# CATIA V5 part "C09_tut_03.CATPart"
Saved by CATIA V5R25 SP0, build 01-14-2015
Part number: Part1
Bounding box of the stored display mesh (mm): x 0 to 224, y -87.769 to 88.937, z 0 to 67.086
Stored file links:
  E:\ashutosh\Academics\Catia\CATIA V5-6R2013_partfiles\Tutorials_ver_2\C09_tut_03.CATPart
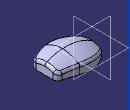
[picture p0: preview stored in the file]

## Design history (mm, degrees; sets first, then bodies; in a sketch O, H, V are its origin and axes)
Body1 (main body)
  Sketch1 on xy-plane, origin (0, 0, 0), H (1, 0, 0), V (0, 1, 0)
    arc A1 centre (95, -36.2404) radius 125 from (0, 45) to (139.6657, 80.5071) cw
    point P1 (95, -36.2404)
    point P2 (0, 45)
    arc A2 centre (289.027, 470.911) radius 418 from (139.6657, 80.5071) to (224, 58) ccw
    point P5 (224, 58)
    radius A1 = 125
    distance P2 H = 45
    distance P2 P5 H = 224
    radius A2 = 418
    distance P5 H = 58
    distance P1 V = 95
    coincidence: P2 V
    tangency: A2 A1
  Sketch2 on xy-plane, origin (0, 0, 0), H (1, 0, 0), V (0, 1, 0)
    axis line L1 (0, -58) -> (224, -58)
    point P1 (0, -58)
    point P2 (224, -58)
    arc A1 centre (112, 154.264) radius 240 from (0, -58) to (224, -58) ccw
    length L1 = 224
    radius A1 = 240
    distance H L1 = 58
    coincidence: P1 V
    horizontal: L1 H
  Sketch3 on zx-plane, origin (0, 0, 0), H (-1, 0, 0), V (0, 0, 1)
    arc A1 centre (-126.7082, -167.9142) radius 235 from (0, 30) to (-224, 46) ccw
    point P2 (0, 30)
    point P3 (-224, 46)
    axis line L1 (-224, 46) -> (-224, 0)
    point P4 (-224, 0)
    radius A1 = 235
    distance P2 H = 30
    length L1 = 46
    distance P2 P3 H = 224
    coincidence: P2 V, P4 H
    vertical: L1 V
  Sketch4 on yz-plane, origin (0, 0, 0), H (0, 1, 0), V (0, 0, 1)
    point P1 (45, 0)
    line L1 (45, 0) -> (45, 18.2879)
    point P3 (-58, 0)
    line L2 (-58, 0) -> (-58, 18.9081)
    arc A1 centre (-7.1526, -89.7866) radius 120 from (-58, 18.9081) to (45, 18.2879) cw
    point P6 (0, 30)
    line L3 (45, 0) -> (-58, 0)
    reference projected point E1 (-58, 0) from Sketch2.P1
    reference projected point E2 (45, 0) from Sketch1.P2
    reference projected point E3 (0, 30) from Sketch3.P2
    radius A1 = 120
    coincidence: P1 H, P3 H, A1 P6, P6 V, P3 E1, P1 E2, P6 E3
    vertical: L1 V, L2 V
    horizontal: L3 H
  Plane1: type 3Points, Element1 Sketch2.P2, Element2 Sketch3.P3, Element3 Sketch1.P5
  Sketch5 on Plane1, origin (224, 0, 0), H (0, -1, 0), V (0, 0, 1)
    point P1 (-58, 0)
    line L1 (-58, 0) -> (58, 0)
    point P2 (58, 0)
    line L2 (58, 0) -> (58, 29.9794)
    arc A1 centre (0, -67) radius 113 from (58, 29.9794) to (-58, 29.9794) ccw
    point P5 (0, 46)
    line L3 (-58, 29.9794) -> (-58, 0)
    reference projected point E1 (-58, 0) from Sketch1.P5
    reference projected point E2 (58, 0) from Sketch2.P2
    reference projected point E3 (0, 46) from Sketch3.P3
    axis line L4 (58, 29.9794) -> (-58, 29.9794)
    radius A1 = 113
    coincidence: P1 H, A1 P5, P5 V, P1 E1, P2 E2, P5 E3
    horizontal: L1 H, L4 H
    vertical: L2 V, L3 V
  Loft1: solid, Sections (Sketch4; Sketch5), Guides (Sketch1; Sketch3; Sketch2)
  Fillet1: radius 25, on edge [face of Loft1 | face of Loft1] (x2)
  Fillet2: radius 15, on edge [face of Loft1 | face of Loft1]
  Shell1: ExtOffset 0, Face (face of Loft1; face of Loft1), IntOffset 3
